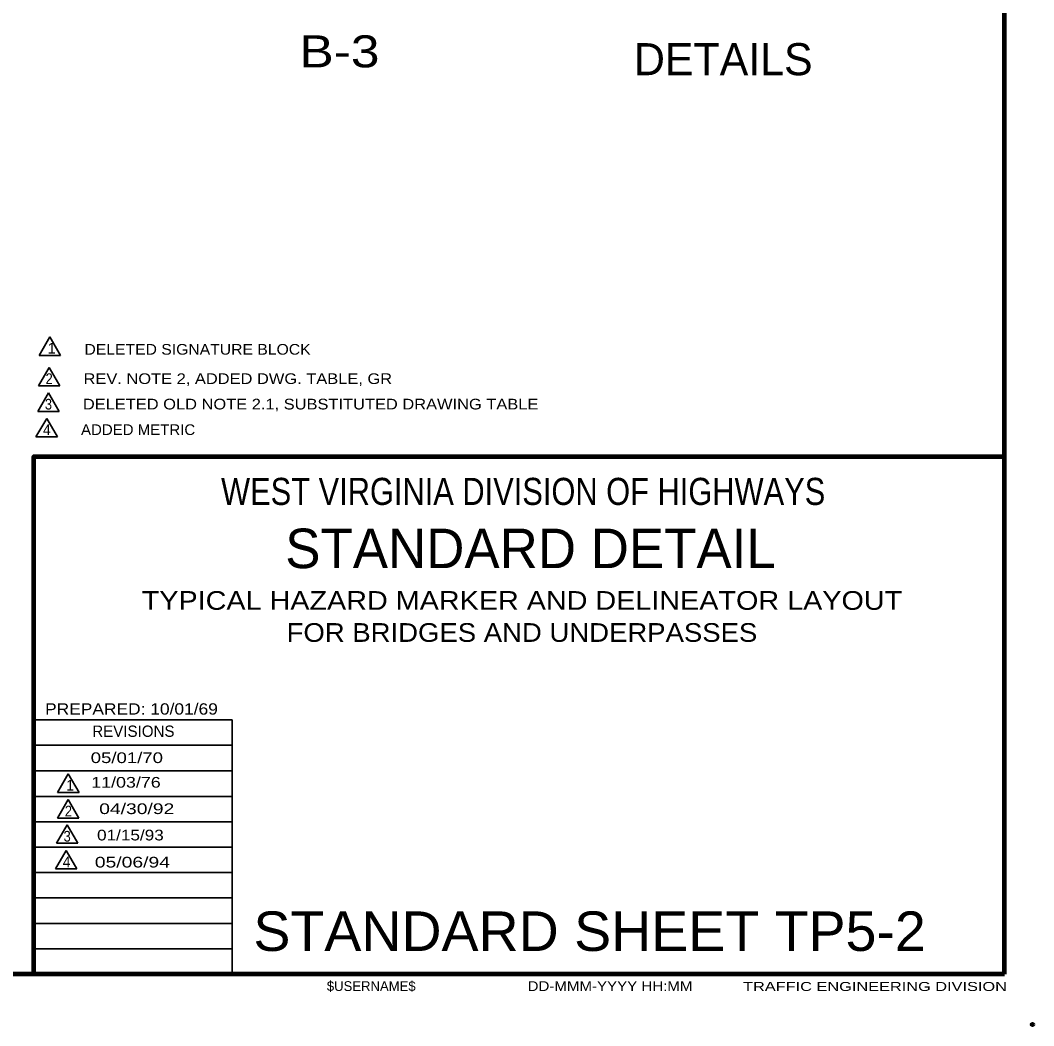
# Model space of a CAD drawing. Extents: x -1843 to -987, y 1073 to 1617.
# Drawn here: x -1214.9 to -987.2, y 1072.7 to 1298.6 of the extents above; entities that cross this region are included whole.
import ezdxf
from ezdxf.enums import TextEntityAlignment as Align

# ---------------------------------------------------------------- set-up
doc = ezdxf.new("R2010")
doc.units = 0
doc.header["$LTSCALE"] = 1.2
doc.header["$PDMODE"] = 32
doc.header["$PDSIZE"] = 0.6
doc.layers.add('1', color=7, linetype='Continuous', lineweight=53)
doc.layers.add('61', color=7, linetype='Continuous', lineweight=35)

msp = doc.modelspace()

# ---------------------------------------------------------------- linework, layer by layer
at = {"layer": '1', "lineweight": 158}
for q in [(-993.822, 1610.418), (-993.822, 1200.618), (-1785.422, 1084.318)]:
    msp.add_line((-993.822, 1084.318), q, dxfattribs=at)
at = {"layer": '1', "lineweight": 13}
msp.add_line((-993.822, 1084.318), (-993.822, 1610.418), dxfattribs=at)
at = {"layer": '1', "lineweight": 35}
for p, q in [((-1208.263, 1227.477), (-1210.663, 1223.321)), ((-1208.263, 1227.477), (-1205.863, 1223.321)), ((-1210.663, 1223.321), (-1205.863, 1223.321)), ((-1208.399, 1220.618), (-1210.799, 1216.461)), ((-1208.399, 1220.618), (-1205.999, 1216.461)), ((-1210.799, 1216.461), (-1205.999, 1216.461)), ((-1208.554, 1214.902), (-1210.954, 1210.745)), ((-1208.554, 1214.902), (-1206.154, 1210.745)), ((-1208.964, 1209.159), (-1211.364, 1205.002)), ((-1210.954, 1210.745), (-1206.154, 1210.745)), ((-1208.964, 1209.159), (-1206.564, 1205.002)), ((-1211.364, 1205.002), (-1206.564, 1205.002)), ((-1167.322, 1135.717), (-1211.822, 1135.717)), ((-1167.322, 1130.018), (-1211.822, 1130.018)), ((-1204.101, 1129.29), (-1206.501, 1125.133)), ((-1204.101, 1129.29), (-1201.701, 1125.133)), ((-1206.501, 1125.133), (-1201.701, 1125.133)), ((-1167.322, 1124.217), (-1211.822, 1124.217)), ((-1204.126, 1123.528), (-1206.526, 1119.371)), ((-1204.126, 1123.528), (-1201.726, 1119.371)), ((-1167.322, 1118.518), (-1211.822, 1118.518)), ((-1206.526, 1119.371), (-1201.726, 1119.371)), ((-1204.394, 1117.88), (-1206.794, 1113.723)), ((-1204.394, 1117.88), (-1201.994, 1113.723)), ((-1206.794, 1113.723), (-1201.994, 1113.723)), ((-1167.322, 1112.818), (-1211.822, 1112.818)), ((-1204.575, 1112.104), (-1206.975, 1107.947)), ((-1204.575, 1112.104), (-1202.175, 1107.947)), ((-1167.322, 1107.118), (-1211.822, 1107.118)), ((-1206.975, 1107.947), (-1202.175, 1107.947)), ((-1167.322, 1101.418), (-1211.822, 1101.418)), ((-1167.322, 1095.717), (-1211.822, 1095.717)), ((-1167.322, 1090.018), (-1211.822, 1090.018))]:
    msp.add_line(p, q, dxfattribs=at)
at = {"layer": '1', "lineweight": 158}
msp.add_lwpolyline([(-1211.822, 1084.318), (-1211.822, 1200.618), (-993.822, 1200.618)], dxfattribs=at)
at = {"layer": '1', "lineweight": 35}
msp.add_lwpolyline([(-1167.322, 1084.318), (-1167.322, 1141.418), (-1211.822, 1141.418)], dxfattribs=at)
at = {"layer": '1'}
msp.add_point((-987.522, 1073.018), dxfattribs=at)
at = {"layer": '61', "lineweight": 53}
for q in [(-1146.522, 1084.318), (-1146.522, 1084.318), (-1146.522, 1084.318), (-1146.222, 1084.318), (-1146.222, 1084.318)]:
    msp.add_line((-993.822, 1084.318), q, dxfattribs=at)

# ---------------------------------------------------------------- texts
at = {"layer": '1'}
for s, height, width, p in [('B-3', 7.2, 1.2, (-1143.187, 1288.021)), ('WEST VIRGINIA DIVISION OF HIGHWAYS', 6.089, 0.85, (-1101.922, 1189.717)), ('TYPICAL HAZARD MARKER AND DELINEATOR LAYOUT', 4.2, 1.15, (-1102.192, 1166.16)), ('FOR BRIDGES AND UNDERPASSES', 4.2, 1.1, (-1102.192, 1158.96))]:
    msp.add_text(s, height=height, dxfattribs=dict(at, width=width)).set_placement(p, align=Align.CENTER)
for s, height, p in [('DETAILS', 7.2, (-1056.961, 1286.264)), ('STANDARD DETAIL', 8.881, (-1100.272, 1175.518))]:
    msp.add_text(s, height=height, dxfattribs=at).set_placement(p, align=Align.CENTER)
for s, height, p in [('1', 2.4, (-1208.736, 1223.731)), ('REVISIONS', 2.537, (-1198.722, 1137.618)), ('1', 2.4, (-1204.573, 1125.543)), ('$USERNAME$', 2.2, (-1146.022, 1080.518))]:
    msp.add_text(s, height=height, dxfattribs=at).set_placement(p)
for s, height, width, p in [('DELETED SIGNATURE BLOCK', 2.4, 1.1, (-1200.479, 1223.476)), ('2', 2.4, 0.9, (-1209.211, 1216.871)), ('REV. NOTE 2, ADDED DWG. TABLE, GR', 2.4, 1.15, (-1200.683, 1216.888)), ('3', 2.4, 0.9, (-1209.365, 1211.155)), ('DELETED OLD NOTE 2.1, SUBSTITUTED DRAWING TABLE', 2.4, 1.15, (-1200.837, 1211.171)), ('4', 2.4, 0.95, (-1209.775, 1205.412)), ('ADDED METRIC', 2.4, 1.05, (-1201.247, 1205.428)), ('PREPARED: 10/01/69', 2.537, 1.15, (-1209.322, 1142.618)), (' 05/01/70', 2.4, 1.3, (-1200.232, 1131.728)), (' 11/03/76', 2.4, 1.25, (-1200.076, 1126.202)), ('04/30/92', 2.4, 1.35, (-1197.163, 1120.271)), ('2', 2.4, 0.9, (-1204.891, 1119.739)), ('3', 2.4, 0.9, (-1205.16, 1114.091)), ('01/15/93', 2.4, 1.2, (-1197.651, 1114.347)), ('4', 2.4, 0.95, (-1205.341, 1108.315)), ('05/06/94', 2.4, 1.35, (-1198.14, 1108.263)), ('STANDARD SHEET TP5-2 ', 8.881, 1.05, (-1162.522, 1089.518)), ('DD-MMM-YYYY HH:MM', 2.2, 1.15, (-1100.922, 1080.518)), ('TRAFFIC ENGINEERING DIVISION', 2.031, 1.35, (-1052.522, 1080.518))]:
    msp.add_text(s, height=height, dxfattribs=dict(at, width=width)).set_placement(p)

doc.saveas('drawing.dxf')
